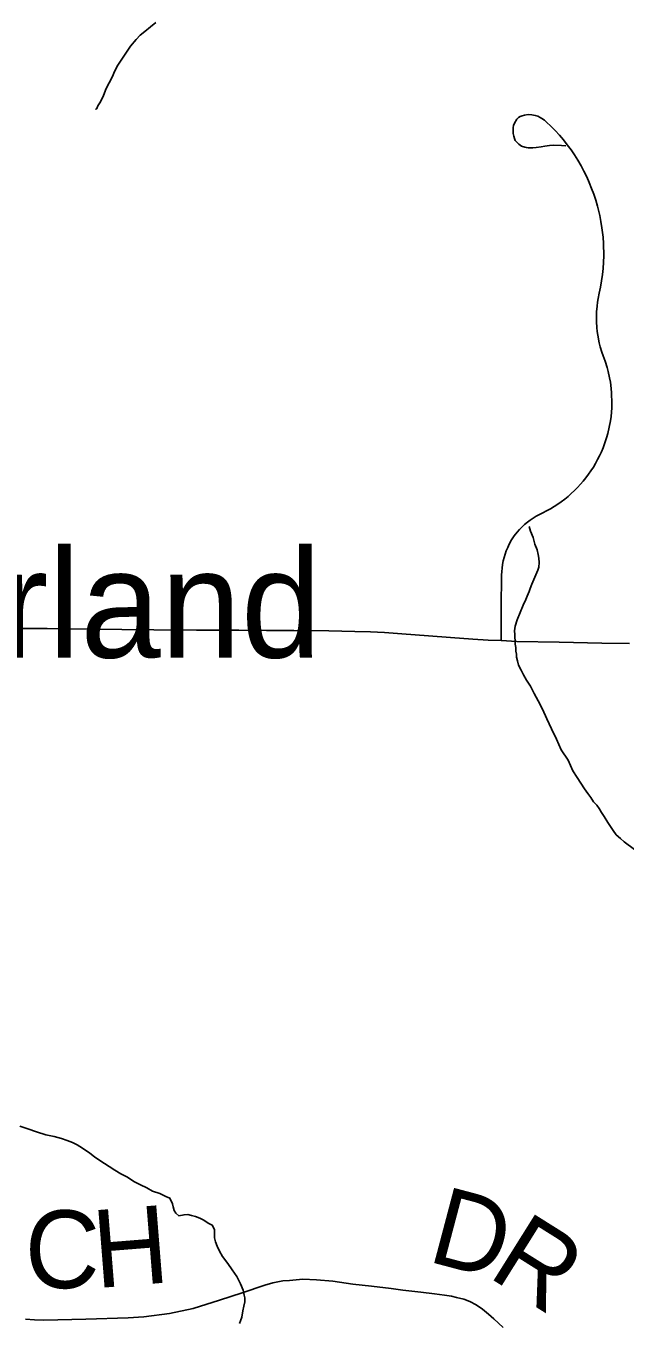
# Model space of a CAD drawing. Extents: x 103424 to 290657, y 38711 to 110967.
# Drawn here: x 110509 to 112838, y 76283 to 81319 of the extents above; entities that cross this region are included whole.
import ezdxf

# ---------------------------------------------------------------- set-up
doc = ezdxf.new("R2010")
doc.units = 0
for name, color, linetype in [('GM_X_Minor_River', 7, 'Continuous'), ('GM_X_Township_Road', 7, 'Continuous'), ('GM_X_Township_Road_Text', 7, 'Continuous'), ('GM_X_Unincorporated_Text', 7, 'Continuous'), ('GM_X_US_Route', 7, 'Continuous'), ('SC_Scratch1', 7, 'Continuous')]:
    doc.layers.add(name, color=color, linetype=linetype)

msp = doc.modelspace()

# ---------------------------------------------------------------- linework, layer by layer
at = {"layer": 'GM_X_Minor_River'}
for points in [[(111013.6, 81332.3), (110993.5, 81315.9), (110971.5, 81297.5), (110953.5, 81283.2), (110937.6, 81266.8), (110915.7, 81240.4), (110866, 81167.1), (110854.2, 81144.8), (110844.4, 81120.5), (110832.5, 81098.1), (110820.6, 81075.8), (110810.8, 81049.4), (110799, 81025.1), (110789.1, 81008.8), (110785.2, 80998.7), (110781.2, 80996.6), (110779.2, 80994.6)], [(112408.3, 78970.7), (112410.1, 78988.9), (112417.9, 79013.2), (112429.7, 79041.6), (112441.5, 79070), (112451.3, 79092.3), (112457.2, 79104.5), (112465.1, 79122.7), (112469, 79134.9), (112474.9, 79151.1), (112498.5, 79205.9), (112502.4, 79218.1), (112504.2, 79236.2), (112502, 79252.4), (112499.8, 79266.5), (112495.5, 79284.6), (112487.2, 79306.8), (112480.8, 79333), (112470.5, 79357.1), (112464.7, 79375.2)], [(112874.6, 78120.9), (112833.9, 78150.8), (112819.6, 78164.8), (112803.2, 78178.7), (112790.9, 78194.8), (112780.7, 78210.8), (112770.4, 78226.9), (112756, 78249), (112745.7, 78265), (112737.4, 78281.1), (112727.2, 78293.1), (112714.9, 78307.1), (112704.6, 78323.2), (112692.3, 78339.2), (112680, 78357.3), (112665.6, 78379.4), (112651.2, 78401.4), (112634.7, 78427.5), (112616.1, 78467.7), (112589.4, 78507.9), (112570.7, 78550.1), (112552.1, 78590.3), (112533.5, 78628.5), (112516.9, 78666.7), (112500.3, 78698.9), (112483.8, 78727), (112469.4, 78755.1), (112455, 78779.2), (112442.6, 78799.3), (112434.3, 78817.4), (112424, 78837.5), (112419.8, 78853.6), (112415.6, 78867.7), (112415.4, 78879.8), (112413.3, 78891.9), (112413.1, 78906.1), (112410.9, 78918.2), (112410.8, 78932.3), (112408.6, 78946.4), (112408.5, 78956.5), (112408.3, 78970.7)], [(110485.8, 77046.6), (110516.2, 77036.8), (110550.6, 77025), (110587.1, 77013.3), (110619.5, 77007.5), (110647.9, 76999.7), (110670.2, 76991.9), (110690.5, 76984), (110708.8, 76974.1), (110729.1, 76962.2), (110757.6, 76942.2), (110775.9, 76928.3), (110796.3, 76914.4), (110814.6, 76902.4), (110832.9, 76890.5), (110855.3, 76876.6), (110877.7, 76862.7), (110904.1, 76848.8), (110928.5, 76832.9), (110954.9, 76819), (110979.3, 76807.1), (111001.7, 76795.2), (111030.1, 76785.4), (111052.4, 76773.5), (111068.6, 76767.6), (111079, 76745.5), (111081.1, 76733.4), (111085.4, 76719.3), (111091.5, 76709.2), (111103.8, 76699.3), (111123.9, 76703.5), (111138.1, 76703.7), (111152.2, 76699.8), (111168.4, 76695.9), (111184.7, 76690), (111200.9, 76682.1), (111217.2, 76670.1), (111233.5, 76662.2), (111241.7, 76646.1), (111241.9, 76627.9), (111242.1, 76613.8), (111246.3, 76597.7), (111252.6, 76581.6), (111260.9, 76561.5), (111273.2, 76541.4), (111293.8, 76513.3), (111310.2, 76489.2), (111328.7, 76463.2), (111343.1, 76435), (111353.5, 76410.9), (111357.8, 76390.7), (111359.9, 76380.7), (111360.1, 76364.5), (111356.3, 76348.3), (111352.4, 76330.1), (111348.7, 76305.8), (111342.8, 76291.6), (111338.9, 76281.5)]]:
    msp.add_lwpolyline(points, dxfattribs=at)
at = {"layer": 'GM_X_Township_Road'}
for points in [[(112355.7, 78932.8), (112356.6, 79059.7), (112357.5, 79186.7), (112358, 79200.6), (112359.3, 79214.4), (112361.3, 79228.2), (112363.8, 79241.9), (112367.1, 79255.4), (112371.4, 79268.7), (112375.9, 79281.8), (112381.5, 79294.6), (112387.5, 79307.1), (112396.6, 79323.3), (112406.9, 79338.8), (112418.3, 79353.5), (112427.3, 79364), (112437.2, 79374), (112447.2, 79383.5), (112457.8, 79392.4), (112468.9, 79400.8), (112480.5, 79408.6), (112492.5, 79415.8), (112504.6, 79422.3), (112518, 79428.7), (112532.8, 79436.3), (112547.4, 79444.5), (112561.8, 79453.1), (112575.9, 79462.3), (112589.5, 79472), (112602.8, 79482.1), (112615.9, 79492.7), (112628.5, 79503.7), (112640.6, 79515.1), (112652.4, 79527), (112664, 79539.4), (112674.8, 79552), (112685.4, 79565.1), (112695.5, 79578.5), (112705.1, 79592.2), (112714.2, 79606.3), (112722.7, 79620.7), (112730.8, 79635.4), (112738.3, 79650.3), (112745.4, 79665.6), (112751.9, 79681), (112757.7, 79696.6), (112765.8, 79720.5), (112770.4, 79736.6), (112776.2, 79761.1), (112780.7, 79785.8), (112783, 79802.4), (112784.7, 79819.1), (112785.7, 79835.8), (112786.3, 79852.6), (112785, 79894.4), (112783.5, 79911.1), (112780.3, 79936), (112777.3, 79952.5), (112771.7, 79977), (112767.4, 79993.2), (112759.7, 80017.2), (112752.1, 80037.7), (112747.3, 80052), (112740.8, 80073.9), (112737.3, 80088.5), (112731.5, 80118.3), (112729.5, 80133.3), (112728, 80148.4), (112726.5, 80171), (112727, 80208.9), (112728.8, 80231.6), (112730.8, 80246.6), (112733.1, 80261.5), (112737.1, 80281.6), (112742.2, 80305.5), (112746.5, 80329.4), (112749.8, 80353.6), (112752.3, 80377.8), (112753.8, 80402.1), (112754.5, 80426.4), (112753.6, 80475.1), (112751.8, 80499.4), (112747.5, 80535.7), (112743.8, 80559.7), (112739, 80583.6), (112730.5, 80619), (112723.7, 80642.5), (112716.1, 80665.6), (112707.6, 80688.5), (112698.6, 80711), (112688.5, 80733.2), (112677.7, 80755.1), (112666.4, 80776.5), (112654, 80797.6), (112640.9, 80818.2), (112627.4, 80838.3), (112613, 80858), (112597.9, 80877.1), (112582.3, 80895.8), (112566, 80913.8), (112549.6, 80929.6), (112532.7, 80945.8), (112524.6, 80953.1), (112514.7, 80960.5), (112507.9, 80964.1), (112498.1, 80968.9), (112488.2, 80971.9), (112475.3, 80974.1), (112461, 80974.8), (112446.3, 80973), (112437.3, 80970.5), (112429.8, 80967.5), (112423.3, 80963.6), (112416.5, 80957.2), (112407.3, 80941.7), (112404.4, 80933.3), (112402.9, 80924.8), (112402.2, 80917.4), (112402.8, 80901.6), (112405.1, 80891.3), (112407.6, 80882.7), (112411, 80874.8), (112416.9, 80867.5), (112424.6, 80859.7), (112435.6, 80853.1), (112447.8, 80848), (112454.4, 80846.7), (112461.7, 80845.4), (112479, 80846.1), (112491.5, 80847.9), (112511.7, 80850.5), (112525.3, 80852.3), (112543.4, 80854.6), (112558.1, 80855.7), (112590.5, 80854.5), (112607.3, 80853.5)], [(110507.2, 76297.6), (110542.2, 76294.8), (110578.8, 76294.1), (110742.6, 76298.2), (110906.5, 76302.3), (110967.7, 76306.5), (111066.6, 76320.1), (111158.9, 76339.8), (111261.7, 76371.8), (111350, 76400.6), (111438.3, 76429.5), (111468.6, 76438.8), (111507.3, 76446.3), (111533.7, 76448.4), (111585.4, 76452.6), (111638.7, 76450.7), (111701.4, 76445.1), (111779.2, 76434.1), (111852.7, 76425.3), (111928, 76416.3), (111973.4, 76410.8), (112043.5, 76402.4), (112096.4, 76396), (112135.6, 76390.8), (112163.5, 76386.6), (112182.9, 76382.2), (112210.6, 76375), (112234.9, 76365.9), (112258.4, 76353.8), (112283.8, 76336.5), (112307.1, 76317.2), (112327.8, 76298.7), (112364, 76265.7)]]:
    msp.add_lwpolyline(points, dxfattribs=at)
at = {"layer": 'GM_X_US_Route'}
msp.add_lwpolyline([(110428.2, 78979.7), (110591.5, 78979.2), (110756.5, 78977.4), (110881.6, 78976.1), (111006.6, 78974.7), (111171.7, 78973.7), (111336.7, 78972.6), (111443.7, 78971.9), (111550.7, 78971.2), (111686.9, 78970), (111787.3, 78968.4), (111848.3, 78966.6), (111902.6, 78964.5), (111969.7, 78959.5), (112073.2, 78951.3), (112159.6, 78944.8), (112245.9, 78938.3), (112305.8, 78934.8), (112355.7, 78932.8), (112416.6, 78929.7), (112581.6, 78926.4), (112746.7, 78923), (112855.1, 78920.9)], dxfattribs=at)
at = {"layer": 'SC_Scratch1'}
msp.add_lwpolyline([(110428.2, 78979.7), (110591.5, 78979.2), (110756.5, 78977.4), (110881.6, 78976.1), (111006.6, 78974.7), (111171.7, 78973.7), (111336.7, 78972.6), (111443.7, 78971.9), (111550.7, 78971.2), (111686.9, 78970), (111787.3, 78968.4), (111848.3, 78966.6), (111902.6, 78964.5), (111969.7, 78959.5), (112073.2, 78951.3), (112159.6, 78944.8), (112245.9, 78938.3), (112305.8, 78934.8), (112355.7, 78932.8), (112416.6, 78929.7), (112581.6, 78926.4), (112746.7, 78923), (112855.1, 78920.9)], dxfattribs=at)

# ---------------------------------------------------------------- texts
at = {"layer": 'GM_X_Township_Road_Text'}
for s, rotation, p in [('D', 345.1615, (112063.8, 76524.1)), ('C', 359.1962, (110503.1, 76420.5)), ('H', 4.5622, (110781.9, 76418)), ('R', 327.8916, (112298.6, 76465.7))]:
    msp.add_text(s, height=301.9, rotation=rotation, dxfattribs=at).set_placement(p)
at = {"layer": 'GM_X_Unincorporated_Text'}
msp.add_text('Chesterland', height=419.602, rotation=0, dxfattribs=at).set_placement((108631.7, 78866.5))

doc.saveas('drawing.dxf')
